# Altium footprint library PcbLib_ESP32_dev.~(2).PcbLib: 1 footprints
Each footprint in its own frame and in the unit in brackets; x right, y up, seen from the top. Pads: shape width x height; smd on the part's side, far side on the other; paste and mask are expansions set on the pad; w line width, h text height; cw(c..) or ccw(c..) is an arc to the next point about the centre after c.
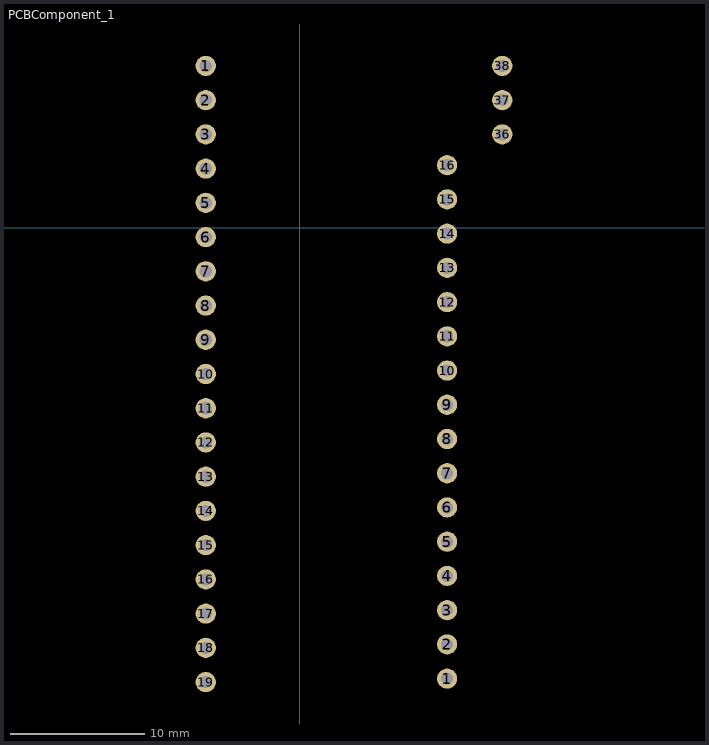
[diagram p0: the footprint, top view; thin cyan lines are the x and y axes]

## PCBComponent_1 [mm]
pads (38):
  round 1.5 hole 0.9: 1(-6.985,12) 1(10.922,-33.463) 2(-6.985,9.46) 2(10.922,-30.923) 3(-6.985,6.92) 3(10.922,-28.383) 4(-6.985,4.38) 4(10.922,-25.843) 5(-6.985,1.84) 5(10.922,-23.303) 6(-6.985,-0.7) 6(10.922,-20.763) 7(-6.985,-3.24) 7(10.922,-18.223) 8(-6.985,-5.78) 8(10.922,-15.683) 9(-6.985,-8.32) 9(10.922,-13.143) 10(-6.985,-10.86) 10(10.922,-10.603) 11(-6.985,-13.4) 11(10.922,-8.063) 12(-6.985,-15.94) 12(10.922,-5.523) 13(-6.985,-18.48) 13(10.922,-2.983) 14(-6.985,-21.02) 14(10.922,-0.443) 15(-6.985,-23.56) 15(10.922,2.097) 16(-6.985,-26.1) 16(10.922,4.637) 17(-6.985,-28.64) 18(-6.985,-31.18) 19(-6.985,-33.72) 36(15.015,6.92) 37(15.015,9.46) 38(15.015,12)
